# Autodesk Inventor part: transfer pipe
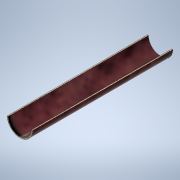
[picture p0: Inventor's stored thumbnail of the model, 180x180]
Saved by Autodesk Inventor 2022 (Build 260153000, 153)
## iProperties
Created: 2021-06
Part Number: transfer pipe
Material: Generic
Document SubType Name: Modeling
Designer: Dell
Density: 1 g/cm^3
Appearance: Default
Author: Dell
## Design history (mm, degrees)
sketch "Sketch1"
  geometry: L1 (-11.5, 0)-(-12.5, 0); L2 (11.5, 0)-(12.5, 0); A1 r 12.5 centre (0, 0) between (-12.5, 0) and (12.5, 0); A2 r 11.5 centre (0, 0) between (-11.5, 0) and (11.5, 0); 1 further point
  constraints: 4 end point, 4 point on circle, 2 centre point, 1 coincident, 1 collinear, 1 horizontal
  dimensions: "d0" = 12.5 radius of A1; "d1" = 1 radial gap between concentric circles of A1 A2
extrude "Extrusion1" new body sketch "Sketch1" distance "d2" = 138; taper "d3" = 0 deg
body "Solid1"
